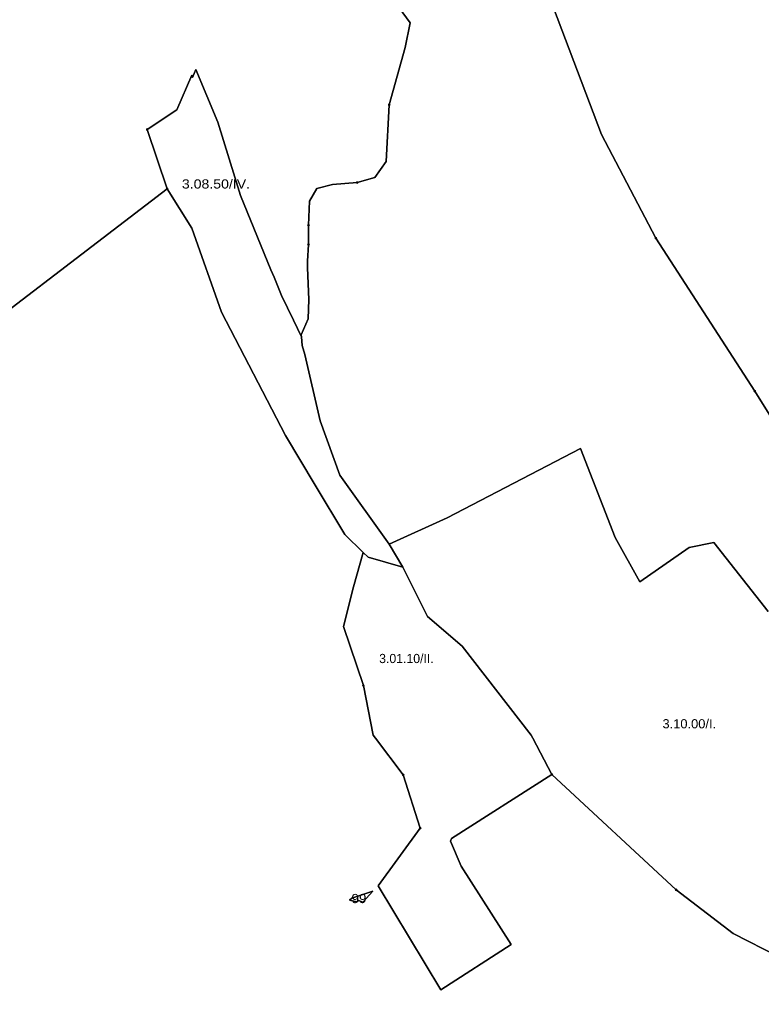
# Model space of a CAD drawing. Extents: x -650455 to -642254, y -1075222 to -1066610.
# Drawn here: x -647687 to -646878, y -1072281 to -1071216 of the extents above; entities that cross this region are included whole.
import ezdxf
from ezdxf.enums import TextEntityAlignment as Align

# ---------------------------------------------------------------- set-up
doc = ezdxf.new("R2010")
doc.units = 0
doc.header["$LTSCALE"] = 4
doc.header["$PDMODE"] = 32
doc.header["$PDSIZE"] = 2
for name, color, linetype, lineweight in [('1', 7, 'Continuous', 25), ('11', 7, 'Continuous', 13), ('12', 7, 'Continuous', 13), ('14', 7, 'Continuous', 13), ('16', 7, 'Continuous', 13)]:
    doc.layers.add(name, color=color, linetype=linetype, lineweight=lineweight)
doc.layers.add('2', color=7, linetype='Continuous')

msp = doc.modelspace()

# ---------------------------------------------------------------- linework, layer by layer
at = {"layer": '1'}
for points in [[(-647412.981, -1071489.088), (-647446.149, -1071408.082), (-647470.706, -1071328.032), (-647494.813, -1071270.777), (-647498.258, -1071279.39), (-647499.23, -1071276.872), (-647515.389, -1071314.575), (-647547.706, -1071336.12), (-647526.161, -1071400.754), (-647800.855, -1071610.814), (-647801.949, -1071610.478), (-647870.875, -1071589.27), (-647903.192, -1071562.339), (-647919.351, -1071530.022), (-647913.965, -1071497.705), (-647903.192, -1071460.002), (-647881.648, -1071406.14), (-647897.806, -1071357.665), (-647773.924, -1071271.486), (-647788.736, -1071241.189), (-647806.937, -1071195.687)], [(-647277.051, -1071198.1), (-647260.893, -1071219.644), (-647266.279, -1071246.575), (-647283.784, -1071309.189), (-647287.224, -1071371.123), (-647299.444, -1071388.627), (-647318.899, -1071394.049), (-647345.688, -1071395.963), (-647362.91, -1071400.428), (-647370.883, -1071414.141), (-647371.84, -1071440.612), (-647371.84, -1071461.661), (-647372.796, -1071479.84), (-647372.796, -1071487.175), (-647371.521, -1071521.618), (-647372.159, -1071542.667), (-647379.813, -1071560.208), (-647379.646, -1071562.215), (-647388.105, -1071543.943), (-647401.5, -1071517.154), (-647409.473, -1071497.38), (-647412.981, -1071489.088)], [(-646870.396, -1071861.944), (-646929.643, -1071786.538), (-646956.574, -1071791.924), (-647010.436, -1071829.627), (-647037.367, -1071781.152), (-647075.07, -1071684.201), (-647220.496, -1071759.607), (-647283.784, -1071788.558), (-647337.645, -1071713.152), (-647359.19, -1071653.904), (-647375.906, -1071581.469), (-647378.856, -1071571.689), (-647379.646, -1071562.215), (-647379.813, -1071560.208), (-647372.159, -1071542.667), (-647371.521, -1071521.618), (-647372.796, -1071487.175), (-647372.796, -1071479.84), (-647371.84, -1071461.661), (-647371.84, -1071440.612), (-647370.883, -1071414.141), (-647362.91, -1071400.428), (-647345.688, -1071395.963), (-647318.899, -1071394.049), (-647299.444, -1071388.627), (-647287.224, -1071371.123), (-647283.784, -1071309.189), (-647266.279, -1071246.575), (-647260.893, -1071219.644), (-647277.051, -1071198.1)], [(-647052.179, -1071341.506), (-647104.694, -1071203.486)], [(-647104.694, -1071203.486), (-647052.179, -1071341.506), (-646992.931, -1071454.616), (-646885.208, -1071621.587), (-646804.415, -1071750.855)], [(-646804.415, -1071750.855), (-646885.208, -1071621.587), (-646992.931, -1071454.616), (-647052.179, -1071341.506)], [(-647800.855, -1071610.814), (-647526.161, -1071400.754), (-647499.23, -1071443.843), (-647466.913, -1071535.408), (-647396.893, -1071670.062), (-647364.576, -1071723.924)], [(-646859, -1072238.5), (-646908.5, -1072213.001), (-646971, -1072165.5), (-647106.5, -1072039.5), (-647127.153, -1072000), (-647128.931, -1071996.598), (-647204.338, -1071899.647), (-647242.041, -1071867.33), (-647268.972, -1071813.469), (-647283.784, -1071788.558), (-647220.496, -1071759.607), (-647075.07, -1071684.201), (-647037.367, -1071781.152), (-647010.436, -1071829.627), (-646956.574, -1071791.924), (-646929.643, -1071786.538), (-646870.396, -1071861.944)], [(-647364.576, -1071723.924), (-647332.259, -1071777.785), (-647312.093, -1071797.421)], [(-647312.093, -1071797.421), (-647322.833, -1071835.013), (-647333.606, -1071878.103), (-647312.061, -1071942.737), (-647301.289, -1071996.598), (-647298.718, -1072000), (-647268.5, -1072040), (-647250, -1072098), (-647296, -1072161), (-647227.5, -1072274.5), (-647151, -1072225.001), (-647205.5, -1072139.501), (-647217, -1072112.5), (-647216, -1072109.5), (-647106.5, -1072039.5), (-646971, -1072165.5), (-646908.5, -1072213.001), (-646859, -1072238.5)]]:
    msp.add_lwpolyline(points, dxfattribs=at)
for points in [[(-647379.646, -1071562.215), (-647378.856, -1071571.689), (-647375.906, -1071581.469), (-647359.19, -1071653.904), (-647337.645, -1071713.152), (-647283.784, -1071788.558), (-647268.972, -1071813.469), (-647306.675, -1071802.696), (-647312.093, -1071797.421), (-647332.259, -1071777.785), (-647364.576, -1071723.924), (-647396.893, -1071670.062), (-647466.913, -1071535.408), (-647499.23, -1071443.843), (-647526.161, -1071400.754), (-647547.706, -1071336.12), (-647515.389, -1071314.575), (-647499.23, -1071276.872), (-647498.258, -1071279.39), (-647494.813, -1071270.777), (-647470.706, -1071328.032), (-647446.149, -1071408.082), (-647412.981, -1071489.088), (-647409.473, -1071497.38), (-647401.5, -1071517.154), (-647388.105, -1071543.943)], [(-647268.972, -1071813.469), (-647242.041, -1071867.33), (-647204.338, -1071899.647), (-647128.931, -1071996.598), (-647127.153, -1072000), (-647106.5, -1072039.5), (-647216, -1072109.5), (-647217, -1072112.5), (-647205.5, -1072139.501), (-647151, -1072225.001), (-647227.5, -1072274.5), (-647296, -1072161), (-647250, -1072098), (-647268.5, -1072040), (-647298.718, -1072000), (-647301.289, -1071996.598), (-647312.061, -1071942.737), (-647333.606, -1071878.103), (-647322.833, -1071835.013), (-647312.093, -1071797.421), (-647306.675, -1071802.696)], [(-647301.629, -1072166.951), (-647312.731, -1072178.69), (-647317.33, -1072176.99), (-647318.97, -1072178.43), (-647327.05, -1072176.85), (-647324.44, -1072174.5)], [(-647301.629, -1072166.951), (-647324.44, -1072174.5), (-647327.05, -1072176.85), (-647318.97, -1072178.43), (-647317.33, -1072176.99), (-647312.731, -1072178.69)]]:
    msp.add_lwpolyline(points, close=True, dxfattribs=at)
at = {"layer": '11'}
for points in [[(-647547.706, -1070654.771), (-647515.389, -1070730.177), (-647460.18, -1070837.227), (-647390.16, -1070966.495), (-647320.14, -1071068.832), (-647244.734, -1071176.555), (-647277.051, -1071198.1), (-647260.893, -1071219.644), (-647266.279, -1071246.575), (-647283.784, -1071309.189), (-647287.224, -1071371.123), (-647299.444, -1071388.627), (-647318.899, -1071394.049), (-647345.688, -1071395.963), (-647362.91, -1071400.428), (-647370.883, -1071414.141), (-647371.84, -1071440.612), (-647371.84, -1071461.661)], [(-646992.931, -1071454.616), (-647052.179, -1071341.506), (-647104.694, -1071203.486), (-647131.625, -1071160.397), (-647158.555, -1071128.08), (-647180.1, -1071041.901), (-647207.031, -1070971.881)], [(-647526.161, -1071400.754), (-647800.855, -1071610.814), (-647801.949, -1071610.478), (-647799.782, -1071650.366), (-647789.455, -1071675.321), (-647779.56, -1071698.124), (-647786.013, -1071719.637), (-647794.619, -1071750.616), (-647797.63, -1071786.328), (-647789.455, -1071836.453), (-647780.85, -1071882.921), (-647775.687, -1071897.12), (-647747.29, -1071974.351), (-647744.278, -1072000.167), (-647701.628, -1072109.378), (-647917.5, -1072238.5), (-647970, -1072276), (-647994, -1072324), (-648000.504, -1072347.414)], [(-647312.061, -1071942.737), (-647333.606, -1071878.103), (-647322.833, -1071835.013), (-647312.093, -1071797.421), (-647332.259, -1071777.785), (-647364.576, -1071723.924), (-647396.893, -1071670.062), (-647466.913, -1071535.408), (-647499.23, -1071443.843), (-647526.161, -1071400.754)], [(-646698.038, -1071931.964), (-646735.742, -1071888.875), (-646762.673, -1071818.855), (-646804.415, -1071750.855), (-646885.208, -1071621.587), (-646992.931, -1071454.616)], [(-647371.84, -1071461.661), (-647372.796, -1071479.84), (-647372.796, -1071487.175), (-647371.521, -1071521.618), (-647372.159, -1071542.667), (-647379.813, -1071560.208), (-647379.646, -1071562.215), (-647378.856, -1071571.689), (-647375.906, -1071581.469), (-647359.19, -1071653.904), (-647337.645, -1071713.152), (-647283.784, -1071788.558), (-647220.496, -1071759.607), (-647075.07, -1071684.201), (-647037.367, -1071781.152), (-647010.436, -1071829.627), (-646956.574, -1071791.924), (-646929.643, -1071786.538), (-646870.396, -1071861.944)], [(-646870.396, -1071861.944), (-646929.643, -1071786.538), (-646956.574, -1071791.924), (-647010.436, -1071829.627), (-647037.367, -1071781.152), (-647075.07, -1071684.201), (-647220.496, -1071759.607), (-647283.784, -1071788.558), (-647268.972, -1071813.469), (-647242.041, -1071867.33), (-647204.338, -1071899.647), (-647128.931, -1071996.598)], [(-647106.5, -1072039.5), (-647216, -1072109.5), (-647217, -1072112.5), (-647205.5, -1072139.501), (-647151, -1072225.001), (-647227.5, -1072274.5), (-647296, -1072161), (-647250, -1072098), (-647268.5, -1072040), (-647298.718, -1072000), (-647301.289, -1071996.598), (-647312.061, -1071942.737)], [(-647128.931, -1071996.598), (-647127.153, -1072000), (-647106.5, -1072039.5), (-646971, -1072165.5)], [(-646725, -1072227.5), (-646766, -1072244.501), (-646794, -1072249.501), (-646830.5, -1072247), (-646859, -1072238.5), (-646908.5, -1072213.001), (-646971, -1072165.5), (-647106.5, -1072039.5)], [(-646971, -1072165.5), (-646908.5, -1072213.001), (-646859, -1072238.5)]]:
    msp.add_lwpolyline(points, dxfattribs=at)
for p in [(-647526.161, -1071400.754), (-646992.931, -1071454.616), (-647371.84, -1071461.661), (-647312.061, -1071942.737), (-647106.5, -1072039.5), (-646971, -1072165.5)]:
    msp.add_point(p, dxfattribs=at)
at = {"layer": '12'}
msp.add_line((-647268.5, -1072040), (-647250, -1072098), dxfattribs=at)
for points in [[(-647283.784, -1071309.189), (-647266.279, -1071246.575), (-647260.893, -1071219.644), (-647277.051, -1071198.1), (-647244.734, -1071176.555), (-647320.14, -1071068.832), (-647390.16, -1070966.495), (-647460.18, -1070837.227), (-647515.389, -1070730.177), (-647547.706, -1070654.771), (-647558.478, -1070606.295), (-647585.409, -1070514.73), (-647601.567, -1070433.938), (-647606.954, -1070347.759), (-647628.498, -1070288.512)], [(-647547.706, -1071336.12), (-647515.389, -1071314.575), (-647499.23, -1071276.872), (-647498.258, -1071279.39), (-647494.813, -1071270.777), (-647470.706, -1071328.032), (-647446.149, -1071408.082), (-647412.981, -1071489.088), (-647409.473, -1071497.38), (-647401.5, -1071517.154), (-647388.105, -1071543.943), (-647379.646, -1071562.215), (-647379.813, -1071560.208), (-647372.159, -1071542.667), (-647371.521, -1071521.618), (-647372.796, -1071487.175), (-647372.796, -1071479.84), (-647371.84, -1071461.661), (-647371.84, -1071440.612)], [(-647318.899, -1071394.049), (-647299.444, -1071388.627), (-647287.224, -1071371.123), (-647283.784, -1071309.189)], [(-647800.855, -1071610.814), (-647526.161, -1071400.754), (-647547.706, -1071336.12)], [(-647371.84, -1071440.612), (-647370.883, -1071414.141), (-647362.91, -1071400.428), (-647345.688, -1071395.963), (-647318.899, -1071394.049)], [(-647250, -1072098), (-647296, -1072161), (-647227.5, -1072274.5), (-647151, -1072225.001), (-647205.5, -1072139.501), (-647217, -1072112.5), (-647216, -1072109.5), (-647106.5, -1072039.5), (-647127.153, -1072000), (-647128.931, -1071996.598), (-647204.338, -1071899.647), (-647242.041, -1071867.33), (-647268.972, -1071813.469), (-647306.675, -1071802.696), (-647312.093, -1071797.421), (-647322.833, -1071835.013), (-647333.606, -1071878.103), (-647312.061, -1071942.737), (-647301.289, -1071996.598), (-647298.718, -1072000), (-647268.5, -1072040)]]:
    msp.add_lwpolyline(points, dxfattribs=at)
for p in [(-647283.784, -1071309.189), (-647547.706, -1071336.12), (-647318.899, -1071394.049), (-647371.84, -1071440.612), (-647268.5, -1072040), (-647250, -1072098)]:
    msp.add_point(p, dxfattribs=at)
at = {"layer": '14'}
msp.add_line((-646885.208, -1071621.587), (-646804.415, -1071750.855), dxfattribs=at)
msp.add_lwpolyline([(-647158.555, -1071128.08), (-647131.625, -1071160.397), (-647104.694, -1071203.486), (-647052.179, -1071341.506), (-646992.931, -1071454.616), (-646885.208, -1071621.587)], dxfattribs=at)
msp.add_lwpolyline([(-647466.913, -1071535.408), (-647396.893, -1071670.062), (-647364.576, -1071723.924), (-647332.259, -1071777.785), (-647312.093, -1071797.421), (-647306.675, -1071802.696), (-647268.972, -1071813.469), (-647283.784, -1071788.558), (-647337.645, -1071713.152), (-647359.19, -1071653.904), (-647375.906, -1071581.469), (-647378.856, -1071571.689), (-647379.646, -1071562.215), (-647388.105, -1071543.943), (-647401.5, -1071517.154), (-647409.473, -1071497.38), (-647412.981, -1071489.088), (-647446.149, -1071408.082), (-647470.706, -1071328.032), (-647494.813, -1071270.777), (-647498.258, -1071279.39), (-647499.23, -1071276.872), (-647515.389, -1071314.575), (-647547.706, -1071336.12), (-647526.161, -1071400.754), (-647499.23, -1071443.843)], close=True, dxfattribs=at)
msp.add_point((-646885.208, -1071621.587), dxfattribs=at)
at = {"layer": '16'}
msp.add_lwpolyline([(-647312.731, -1072178.69), (-647301.629, -1072166.951), (-647324.44, -1072174.5), (-647327.05, -1072176.85), (-647318.97, -1072178.43), (-647317.33, -1072176.99)], close=True, dxfattribs=at)

# ---------------------------------------------------------------- texts
at = {"layer": '2'}
for s, width, p in [('3.08.50/IV.', 1.15, (-647472.772, -1071400.523)), ('3.10.00/I.', 1.05, (-646956.534, -1071989.283)), ('99', 1.1, (-647316.831, -1072179.886))]:
    msp.add_text(s, height=10, dxfattribs=dict(at, width=width)).set_placement(p, align=Align.CENTER)
msp.add_text('3.01.10/II.', height=10, dxfattribs=at).set_placement((-647265.052, -1071918.102), align=Align.CENTER)

doc.saveas('drawing.dxf')
